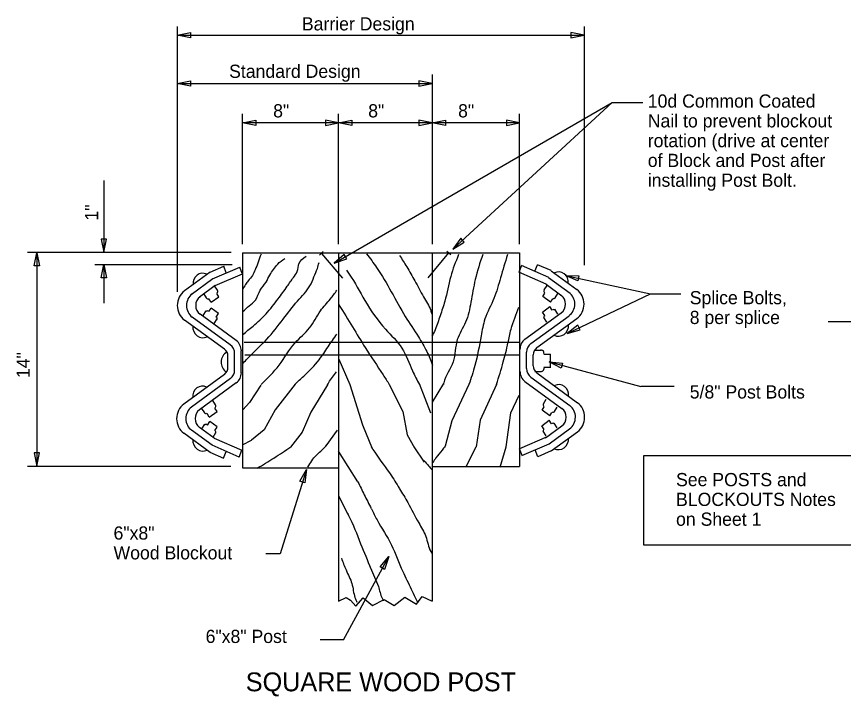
# Model space of a CAD drawing. Extents: x -0.7 to 88.8, y -25.9 to 22.
# Drawn here: x 60.74 to 69.51, y -13.64 to -6.43 of the extents above; entities that cross this region are included whole.
import ezdxf

# ---------------------------------------------------------------- set-up
doc = ezdxf.new("R2010")
doc.units = 0
doc.layers.add('Default', color=7, linetype='Continuous')

msp = doc.modelspace()

# ---------------------------------------------------------------- linework, layer by layer
at = {"layer": 'Default'}
for p, q in [((62.4403, -6.5322), (62.4403, -8.9528)), ((66.758, -6.5322), (66.758, -9.0682)), ((62.4403, -6.6265), (65.1558, -6.6265)), ((65.1558, -6.6265), (66.758, -6.6265)), ((65.1456, -7.0433), (65.1456, -7.5892)), ((65.1456, -7.0433), (65.1456, -8.8427)), ((62.4403, -7.1377), (64.5394, -7.1377)), ((64.5394, -7.1377), (65.1456, -7.1377)), ((65.3633, -8.8963), (67.0547, -7.341)), ((67.0547, -7.341), (67.3813, -7.341)), ((63.1349, -8.8427), (63.1349, -7.4618)), ((64.1531, -8.8427), (64.1531, -7.4618)), ((66.0741, -8.8427), (66.0741, -7.4618)), ((66.0741, -7.5563), (63.1349, -7.5563)), ((61.662, -8.1695), (61.662, -8.9298)), ((60.8517, -8.9298), (63.013, -8.9298)), ((60.9509, -8.9347), (60.9509, -9.6575)), ((63.1349, -8.937), (66.0741, -8.937)), ((63.1349, -8.937), (63.1349, -11.2185)), ((63.9909, -8.9222), (63.9496, -8.9595)), ((63.9726, -8.9413), (64.1933, -9.2065)), ((64.1531, -8.937), (64.1531, -12.6312)), ((65.3199, -8.9358), (65.0991, -9.2012)), ((65.1446, -8.937), (65.1446, -12.6312)), ((65.3016, -8.9168), (65.3429, -8.9542)), ((66.0741, -8.937), (66.0741, -11.205)), ((62.4403, -8.9528), (62.4403, -9.0838)), ((61.5675, -9.0608), (63.0231, -9.0608)), ((61.662, -9.0608), (61.662, -9.4698)), ((62.4403, -9.0838), (62.4403, -9.3505)), ((62.79, -9.1402), (62.934, -9.0773)), ((62.8147, -9.2132), (63.1042, -9.0868)), ((62.9614, -9.1475), (62.9344, -9.0782)), ((63.1304, -9.157), (63.1034, -9.0878)), ((66.0676, -9.1417), (66.0946, -9.0725)), ((66.3832, -9.1978), (66.0938, -9.0715)), ((66.2366, -9.1322), (66.2636, -9.0628)), ((66.408, -9.1248), (66.2641, -9.062)), ((62.7903, -9.1405), (62.5174, -9.3405)), ((62.8173, -9.2117), (62.5872, -9.3803)), ((62.844, -9.2837), (63.1335, -9.1575)), ((66.3541, -9.2685), (66.0646, -9.1422)), ((66.3807, -9.1965), (66.6108, -9.365)), ((66.4077, -9.1252), (66.6806, -9.3252)), ((66.5601, -9.1777), (67.4609, -9.3712)), ((62.8431, -9.2842), (62.6764, -9.4063)), ((62.8676, -9.3322), (62.8374, -9.285)), ((66.3346, -9.3302), (66.3647, -9.283)), ((66.3549, -9.2688), (66.5216, -9.391)), ((62.7517, -9.4148), (62.7226, -9.3692)), ((62.8827, -9.4023), (62.8601, -9.3668)), ((66.3194, -9.4003), (66.3421, -9.3648)), ((66.4504, -9.4128), (66.4795, -9.3672)), ((66.5779, -9.7907), (67.4609, -9.3712)), ((67.4609, -9.3712), (67.7854, -9.3712)), ((62.8005, -9.4612), (62.7774, -9.4248)), ((62.8003, -9.4608), (62.8828, -9.4022)), ((66.4019, -9.4588), (66.3193, -9.4002)), ((66.4016, -9.4592), (66.4248, -9.4228)), ((62.7146, -9.6005), (62.7464, -9.5505)), ((62.7746, -9.5602), (62.7992, -9.5215)), ((62.8777, -9.5792), (62.7991, -9.5217)), ((66.317, -9.564), (66.3956, -9.5067)), ((66.4201, -9.545), (66.3955, -9.5063)), ((66.4801, -9.5853), (66.4483, -9.5353)), ((62.9409, -9.9575), (62.5177, -9.649)), ((63.0041, -9.9125), (62.6002, -9.618)), ((63.0673, -9.8675), (62.6826, -9.587)), ((62.8327, -9.6865), (62.8636, -9.638)), ((62.8536, -9.6177), (62.8775, -9.58)), ((66.1307, -9.8522), (66.5154, -9.5718)), ((66.1939, -9.8972), (66.5978, -9.6028)), ((66.2571, -9.9422), (66.6803, -9.6338)), ((66.3411, -9.6025), (66.3172, -9.565)), ((66.362, -9.6715), (66.3311, -9.6228)), ((60.9509, -9.6575), (60.9509, -11.2)), ((63.1499, -9.8833), (66.0744, -9.8833)), ((63.1209, -10.208), (63.1209, -9.9755)), ((66.0771, -10.1927), (66.0771, -9.9602)), ((66.1479, -10.1632), (66.1479, -9.9898)), ((66.2343, -9.9693), (66.3066, -9.9693)), ((62.9793, -10.149), (62.9793, -10.0347)), ((63.0501, -10.1783), (63.0501, -10.0052)), ((63.0501, -10.0972), (63.0501, -10.0863)), ((63.1572, -10.0193), (66.0707, -10.0193)), ((64.1556, -10.0627), (64.2729, -10.3318)), ((66.1479, -10.0818), (66.1479, -10.071)), ((66.1907, -10.0212), (66.1907, -10.0212)), ((66.2187, -10.1337), (66.2187, -10.0193)), ((66.3298, -10.01), (66.4021, -10.01)), ((66.4031, -10.1497), (66.4031, -10.0112)), ((66.3321, -10.1502), (66.4065, -10.1502)), ((66.3875, -10.0937), (67.359, -10.354)), ((62.9411, -10.226), (62.5107, -10.5415)), ((66.1937, -10.2555), (66.6048, -10.557)), ((66.2357, -10.1937), (66.2978, -10.1937)), ((66.2569, -10.2108), (66.6872, -10.5262)), ((63.0043, -10.2708), (62.5932, -10.5723)), ((63.0676, -10.3158), (62.6758, -10.603)), ((65.0061, -10.3228), (65.1297, -10.6338)), ((65.2666, -10.3227), (65.1472, -10.5198)), ((66.1305, -10.3005), (66.5222, -10.5877)), ((67.7142, -10.354), (67.359, -10.354)), ((62.8477, -10.55), (62.8176, -10.5027)), ((66.327, -10.537), (66.3571, -10.4897)), ((62.7319, -10.6327), (62.7028, -10.587)), ((62.8629, -10.6202), (62.8402, -10.5847)), ((66.3942, -10.6655), (66.3116, -10.607)), ((66.3118, -10.607), (66.3345, -10.5715)), ((66.4427, -10.6195), (66.4718, -10.5738)), ((62.7806, -10.679), (62.7576, -10.6427)), ((62.7805, -10.6787), (62.863, -10.62)), ((66.3941, -10.6658), (66.4171, -10.6297)), ((62.8335, -10.9028), (62.6761, -10.7882)), ((62.7023, -10.8052), (62.734, -10.7552)), ((62.7622, -10.7648), (62.7869, -10.7262)), ((62.8654, -10.7838), (62.7867, -10.7263)), ((62.8412, -10.8223), (62.8651, -10.7848)), ((66.3093, -10.7708), (66.388, -10.7133)), ((66.3335, -10.8093), (66.3096, -10.7717)), ((66.3469, -10.9005), (66.522, -10.7728)), ((66.4125, -10.7518), (66.3878, -10.7132)), ((66.4724, -10.7922), (66.4407, -10.7422)), ((62.7906, -11.0538), (62.5111, -10.8502)), ((62.8114, -10.9778), (62.5936, -10.8192)), ((62.8203, -10.8913), (62.8513, -10.8427)), ((64.0195, -10.9845), (64.1426, -10.8182)), ((66.3544, -10.8782), (66.3234, -10.8297)), ((66.3866, -10.9625), (66.6045, -10.8038)), ((66.4075, -11.0385), (66.6869, -10.8348)), ((62.8335, -10.9025), (63.1271, -11.0305)), ((63.1326, -10.975), (63.2275, -10.9242)), ((66.3646, -10.8872), (66.0709, -11.0153)), ((66.0988, -11.0883), (66.3883, -10.962)), ((62.7883, -11.053), (62.9322, -11.1157)), ((63.0992, -11.1037), (62.8097, -10.9773)), ((62.9314, -11.1155), (62.9597, -11.0428)), ((63.0984, -11.1037), (63.1271, -11.03)), ((64.3588, -11.368), (64.1515, -11.0418)), ((64.9505, -10.9933), (65.0617, -11.158)), ((65.5076, -11.2052), (65.6126, -10.9933)), ((65.8673, -11.2095), (65.9305, -10.9933)), ((66.0996, -11.0883), (66.071, -11.0148)), ((66.2666, -11.1002), (66.2383, -11.0275)), ((66.4097, -11.0377), (66.2658, -11.1005)), ((60.8517, -11.2), (63.0083, -11.2)), ((63.1349, -11.2185), (64.1519, -11.2185)), ((65.1434, -11.205), (66.0721, -11.205)), ((63.8125, -11.2362), (63.5327, -12.1297)), ((64.1515, -11.516), (64.2525, -11.7095)), ((63.5327, -12.1297), (63.3802, -12.1297)), ((64.2059, -13.042), (64.6871, -12.16)), ((64.4926, -12.2803), (64.5769, -12.4753)), ((64.2059, -13.042), (63.9586, -13.042))]:
    msp.add_line(p, q, dxfattribs=at)
for points in [[(62.5803, -6.6545), (62.4403, -6.6265), (62.5803, -6.5985)], [(66.618, -6.6545), (66.758, -6.6265), (66.618, -6.5985)], [(62.5803, -7.1657), (62.4403, -7.1377), (62.5803, -7.1097)], [(65.0056, -7.1657), (65.1456, -7.1377), (65.0056, -7.1097)], [(63.2749, -7.5843), (63.1349, -7.5563), (63.2749, -7.5283)], [(64.0131, -7.5843), (64.1531, -7.5563), (64.0131, -7.5283)], [(64.2931, -7.5843), (64.1531, -7.5563), (64.2931, -7.5283)], [(65.0056, -7.5843), (65.1456, -7.5563), (65.0056, -7.5283)], [(65.2856, -7.5843), (65.1456, -7.5563), (65.2856, -7.5283)], [(65.9341, -7.5843), (66.0741, -7.5563), (65.9341, -7.5283)], [(61.634, -8.7898), (61.662, -8.9298), (61.69, -8.7898)], [(65.4486, -8.7819), (65.3633, -8.8963), (65.4861, -8.8235)], [(60.9229, -9.0747), (60.9509, -8.9347), (60.9789, -9.0747)], [(64.2136, -8.9523), (64.1064, -9.0465), (64.2416, -9.0008)], [(61.634, -9.2008), (61.662, -9.0608), (61.69, -9.2008)], [(66.6912, -9.2342), (66.5601, -9.1777), (66.7029, -9.1794)], [(66.6915, -9.7041), (66.5779, -9.7907), (66.7161, -9.7545)], [(66.5144, -10.1592), (66.3875, -10.0937), (66.5298, -10.1054)], [(60.9229, -11.06), (60.9509, -11.2), (60.9789, -11.06)], [(67.3933, -11.0881), (70.1781, -11.0881), (70.1781, -12.0369), (67.3933, -12.0369)], [(63.7426, -11.3607), (63.8125, -11.2362), (63.7958, -11.378)], [(64.5929, -12.2673), (64.6871, -12.16), (64.6414, -12.2953)]]:
    msp.add_lwpolyline(points, close=True, dxfattribs=at)
for points in [[(64.1064, -9.0465), (67.0547, -7.341)], [(71.1779, -9.1776), (69.5972, -9.6669), (69.3465, -9.6669)], [(63.3267, -10.34), (63.2083, -10.5242), (63.1381, -10.6032)], [(63.6923, -10.328), (63.4802, -10.6032), (63.3618, -10.8137), (63.2275, -10.9242)], [(64.0341, -10.3383), (63.8576, -10.6252), (63.7654, -10.84), (63.6418, -10.9968)], [(64.2729, -10.3318), (64.4059, -10.7612), (64.5105, -11.0115)], [(64.6901, -10.3318), (64.8358, -10.6207), (64.8796, -10.8663), (64.9592, -11.0063)], [(65.536, -10.3318), (65.3535, -10.7172), (65.2829, -10.9883)], [(65.8289, -10.3318), (65.6561, -10.7128), (65.6126, -10.9933)], [(65.9305, -10.9933), (65.9807, -10.6338), (66.0685, -10.4453)], [(64.1531, -12.6312), (64.2341, -12.593), (64.2796, -12.6235), (64.3375, -12.6848), (64.4119, -12.5972), (64.5111, -12.6803), (64.6351, -12.6148), (64.7427, -12.6803), (64.8544, -12.5885), (64.9784, -12.6628), (65.0404, -12.5842), (65.1446, -12.6312)]]:
    msp.add_lwpolyline(points, dxfattribs=at)
for centre, major_axis, start_param, end_param in [((62.71, -9.2595), (0, -0.1065), 2.687211, 4.851441), ((66.488, -9.2442), (0, -0.1065), 1.431744, 3.595974), ((62.6182, -9.4946), (0, -0.1875), 3.747084, 5.680264), ((62.6805, -9.4945), (0, -0.15), 3.747137, 5.680324), ((62.8517, -9.3447), (0, 0.0198), 3.70437, 5.352473), ((66.3505, -9.3427), (0, 0.0198), 0.930712, 2.578815), ((66.4552, -9.4792), (0, -0.1125), 0.602888, 2.536083), ((66.5175, -9.4792), (0, -0.15), 0.602861, 2.536048), ((66.5799, -9.4794), (0, -0.1875), 0.602921, 2.536101), ((62.7429, -9.4945), (0, -0.1125), 3.747102, 5.680297), ((62.7646, -9.4041), (0, -0.0195), 5.247458, 6.879592), ((66.4376, -9.4021), (0, -0.0195), 5.686779, 7.318912), ((62.7588, -9.5737), (0, 0.021), 5.452301, 7.118326), ((66.4359, -9.5586), (0, 0.021), 5.448045, 7.11407), ((62.8445, -9.6362), (0, 0.021), 4.196406, 5.73538), ((66.3502, -9.6211), (0, 0.021), 0.547805, 2.086779), ((62.7132, -9.722), (0, -0.115), 4.640651, 6.714317), ((66.4849, -9.7067), (0, -0.115), 5.852054, 7.925719), ((62.9439, -10.0051), (0, 0.1125), 4.712389, 5.68034), ((62.997, -9.9755), (0, 0.1312), 4.712389, 5.680267), ((66.201, -9.9602), (0, 0.1312), 0.602918, 1.570796), ((66.2542, -9.9898), (0, 0.1125), 0.602846, 1.570796), ((63.0196, -10.0972), (0, -0.12), 3.613765, 5.74142), ((62.8907, -10.0347), (0, 0.0937), 4.712389, 5.680377), ((66.3073, -10.0194), (0, 0.0937), 0.602808, 1.570796), ((66.305, -9.9988), (0, -0.0298), 2.729343, 3.43401), ((66.3039, -9.9996), (0, 0.03), 4.574534, 6.237266), ((66.305, -9.9988), (0, -0.0298), 1.431351, 1.439211), ((62.8907, -10.149), (0, -0.0937), 0.605563, 1.570796), ((66.2542, -10.1631), (0, -0.1125), 4.712389, 5.677535), ((66.3073, -10.1337), (0, -0.0937), 4.712389, 5.677623), ((66.3027, -10.162), (0, -0.0326), 6.093782, 8.000338), ((62.9439, -10.1784), (0, -0.1125), 0.605651, 1.570796), ((62.997, -10.208), (0, -0.1312), 0.605566, 1.570796), ((66.201, -10.1927), (0, -0.1312), 4.712389, 5.677619), ((62.707, -10.4564), (0, -0.1065), 2.687211, 4.851441), ((66.4911, -10.4411), (0, -0.1065), 1.431744, 3.595974), ((66.5865, -10.6804), (0, -0.1875), 0.602905, 2.536094), ((62.6115, -10.6957), (0, -0.1875), 3.747091, 5.68028), ((62.6739, -10.6956), (0, -0.15), 3.747115, 5.680355), ((62.7363, -10.6955), (0, -0.1125), 3.747102, 5.680258), ((62.8318, -10.5625), (0, 0.0198), 3.70437, 5.352473), ((66.3429, -10.5494), (0, 0.0198), 0.930712, 2.578815), ((66.4618, -10.6802), (0, -0.1125), 0.602927, 2.536083), ((66.5242, -10.6803), (0, -0.15), 0.602831, 2.53607), ((62.7448, -10.622), (0, -0.0195), 5.247458, 6.879592), ((66.4299, -10.6089), (0, -0.0195), 5.686779, 7.318912), ((62.7465, -10.7784), (0, 0.021), 5.452301, 7.118326), ((66.4282, -10.7653), (0, 0.021), 5.448045, 7.11407), ((62.8321, -10.8409), (0, 0.021), 4.196406, 5.73538), ((66.3426, -10.8278), (0, 0.021), 0.547805, 2.086779), ((62.7132, -10.9253), (0, -0.115), 4.640651, 6.714317), ((66.4849, -10.91), (0, -0.115), 5.852054, 7.925719)]:
    msp.add_ellipse(centre, major_axis=major_axis, ratio=0.944544, start_param=start_param, end_param=end_param, dxfattribs=at)
for points in [[(64.4505, -8.946), (64.5558, -9.0922), (64.7121, -9.3498), (64.861, -9.6113), (64.9991, -9.8267), (65.0899, -9.9843), (65.148, -10.1268)], [(63.3296, -8.951), (63.2671, -9.1172), (63.238, -9.175), (63.1943, -9.2327), (63.1653, -9.2712), (63.1326, -9.3288)], [(63.1362, -9.802), (63.2452, -9.7135), (63.3833, -9.5827), (63.5104, -9.425), (63.6086, -9.2903), (63.6739, -9.198), (63.7138, -9.1327), (63.732, -9.0518), (63.8086, -8.9713)], [(63.1362, -9.5595), (63.2052, -9.4982), (63.2706, -9.4365), (63.3216, -9.3327), (63.3833, -9.248), (63.4232, -9.1712), (63.4631, -9.1135), (63.5068, -9.0558), (63.5826, -8.9955)], [(64.7999, -8.9632), (64.8756, -9.0845), (64.9627, -9.2345), (65.0536, -9.4037), (65.1299, -9.546), (65.1407, -9.5845)], [(65.4252, -8.955), (65.3422, -9.1872), (65.2802, -9.4498), (65.2306, -9.603), (65.1769, -9.7518), (65.1437, -9.822)], [(65.6819, -8.9535), (65.6027, -9.2178), (65.5573, -9.4587), (65.4994, -9.673), (65.4125, -9.857), (65.3671, -10.0933), (65.2678, -10.3165), (65.2646, -10.3318)], [(65.9445, -8.9553), (65.8715, -9.2003), (65.8012, -9.4192), (65.7061, -9.638), (65.6647, -9.8175), (65.5986, -10.1327), (65.536, -10.3318)], [(63.1398, -10.1058), (63.238, -10.0057), (63.3906, -9.852), (63.5649, -9.6403), (63.7175, -9.4482), (63.8482, -9.2865), (63.8918, -9.1903), (63.9282, -9.102), (63.9453, -9.0402)], [(64.2356, -9.1197), (64.2651, -9.1613), (64.4323, -9.4422), (64.6503, -9.746), (64.8246, -9.946), (64.9373, -10.1883), (65.0107, -10.3318)], [(63.3325, -10.3318), (63.5212, -10.1288), (63.692, -9.8903), (63.8446, -9.7327), (63.9609, -9.5518), (64.0663, -9.425), (64.1352, -9.3327)], [(64.1561, -9.4883), (64.3016, -9.723), (64.4359, -9.9422), (64.6249, -10.2305), (64.6901, -10.3318)], [(65.8289, -10.3318), (65.9005, -10.0933), (65.9501, -9.892), (65.9831, -9.7475), (66.0659, -9.5112)], [(63.6882, -10.3318), (63.7829, -10.2442), (63.9463, -10.0712), (64.0408, -9.9327), (64.1352, -9.798)], [(64.0341, -10.3383), (64.0481, -10.3135), (64.1316, -10.198)], [(63.2887, -11.2212), (63.4668, -11.1135), (63.647, -10.9933)], [(63.8265, -11.2097), (63.9172, -11.0827), (64.0081, -10.998), (64.0244, -10.9785)], [(64.4991, -10.9933), (64.5359, -11.052), (64.7137, -11.3015), (64.8066, -11.4538)], [(65.2829, -10.9883), (65.2513, -11.03), (65.1851, -11.1132), (65.1521, -11.1615)], [(65.0577, -11.1385), (65.1081, -11.196), (65.1444, -11.2383)], [(64.3578, -11.3662), (64.4243, -11.5028), (64.4994, -11.65)], [(64.7976, -11.4388), (64.8874, -11.586), (65.0032, -11.8005), (65.0776, -11.945), (65.1314, -12.107), (65.1437, -12.1288)], [(64.5004, -11.6518), (64.5607, -11.77), (64.7137, -12.0368), (64.8337, -12.317), (64.9246, -12.5053), (64.966, -12.593), (64.9949, -12.6498)], [(64.2486, -11.702), (64.2589, -11.7218), (64.3871, -12.0238), (64.4958, -12.288)], [(64.1822, -12.1748), (64.2318, -12.3018), (64.2939, -12.4462), (64.3269, -12.595), (64.3476, -12.6432)], [(64.5769, -12.4753), (64.6145, -12.6017), (64.627, -12.6278)]]:
    msp.add_spline(points, degree=3, dxfattribs=at)

# ---------------------------------------------------------------- texts
for s, height, p in [('Barrier Design', 0.14, (63.7634, -6.5756)), ('Standard Design', 0.14, (62.9912, -7.079)), ('10d Common Coated', 0.14, (67.4336, -7.3949)), ('  8"', 0.14, (63.3546, -7.4985)), ('  8"', 0.14, (64.363, -7.4985)), ('  8"', 0.14, (65.3169, -7.4985)), ('Nail to prevent blockout', 0.14, (67.4336, -7.6049)), ('rotation (drive at center', 0.14, (67.4336, -7.8149)), ('of Block and Post after', 0.14, (67.4336, -8.0249)), ('installing Post Bolt.', 0.14, (67.4336, -8.2349)), ('Splice Bolts,', 0.14, (67.8788, -9.4815)), ('8 per splice', 0.14, (67.8788, -9.6915)), ('5/8" Post Bolts', 0.14, (67.8788, -10.482)), ('See POSTS and', 0.14, (67.7334, -11.4125)), ('BLOCKOUTS Notes', 0.14, (67.7334, -11.6225)), ('on Sheet 1', 0.14, (67.7334, -11.8325)), ('6"x8"', 0.14, (61.7648, -11.9793)), ('Wood Blockout', 0.14, (61.7648, -12.1893)), ('6"x8" Post', 0.14, (62.7419, -13.0765)), ('SQUARE WOOD POST', 0.2, (63.168, -13.5891))]:
    msp.add_text(s, height=height, dxfattribs=at).set_placement(p)
for s, p in [('1"', (61.6025, -8.5937)), ('14" ', (60.8757, -10.2649))]:
    msp.add_text(s, height=0.14, rotation=90, dxfattribs=at).set_placement(p)

doc.saveas('drawing.dxf')
